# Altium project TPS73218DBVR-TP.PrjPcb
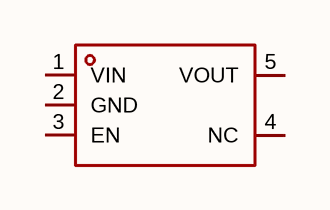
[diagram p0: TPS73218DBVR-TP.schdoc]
1 sheet, 1 parts. Net scope: global (net labels, ports and power ports of the same name join across sheets).

## Sheet TPS73218DBVR-TP.schdoc
size 127 x 101 mm

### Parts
U?  tps73218dbvr-tp  [SOT-23-5_L2.9-W1.6-P0.95-LS2.8-BR]  (value not drawn)

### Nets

Not connected (* = marked no-connect by the designer): U? 1(VIN) 2(GND) 3(EN) 4(NC) 5(VOUT)

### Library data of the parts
U? = tps73218dbvr-tp: 输出极性:正极;工作电压:5.5V;输出电压:1.8V;输出电流:250mA;电源纹波抑制比(PSRR):70dB@(1kHz);输出类型:固定;; Manufacturer: TECH PUBLIC(台舟); AddInBom: yes; ModelId: 7ba65df16e7b4570af156e925f9c37fe; ModelTransform: 114.173,114.173,0,90,0,0,0,0,0; Output Configuration: 正极; Voltage - Supply: 5.5V; Output Voltage: 1.8V; Output Current: 250mA; Voltage Dropout: 260mV@(250mA); standby current: 10uA; Output Type: 固定; Number of Outputs: 1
